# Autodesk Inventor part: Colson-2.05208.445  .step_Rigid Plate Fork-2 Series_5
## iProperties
Created: 2012-08
Part Number: Colson-2.05208.445  .step_Rigid Plate Fork-2 Series_5
Document SubType Name: Modeling
Designer: Administrator
Density: 7.85 g/cm^3
Material: Steel
Mass: 349.623 g
Surface Area: 373.311 cm^2
Volume: 44.5379 cm^3
Author: Administrator
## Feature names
1. Base1
2. Extrusion1
